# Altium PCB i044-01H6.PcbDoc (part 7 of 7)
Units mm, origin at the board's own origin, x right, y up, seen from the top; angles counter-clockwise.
Board outline 42 x 29.01 mm, 8 copper layers (Top Layer, Mid-Layer 1, Mid-Layer 2, Mid-Layer 3, Mid-Layer 4, Mid-Layer 5, Mid-Layer 6, Bottom Layer), stack 1.474 mm thick; 235 components, 197 nets, 1006 pads, 1183 vias.
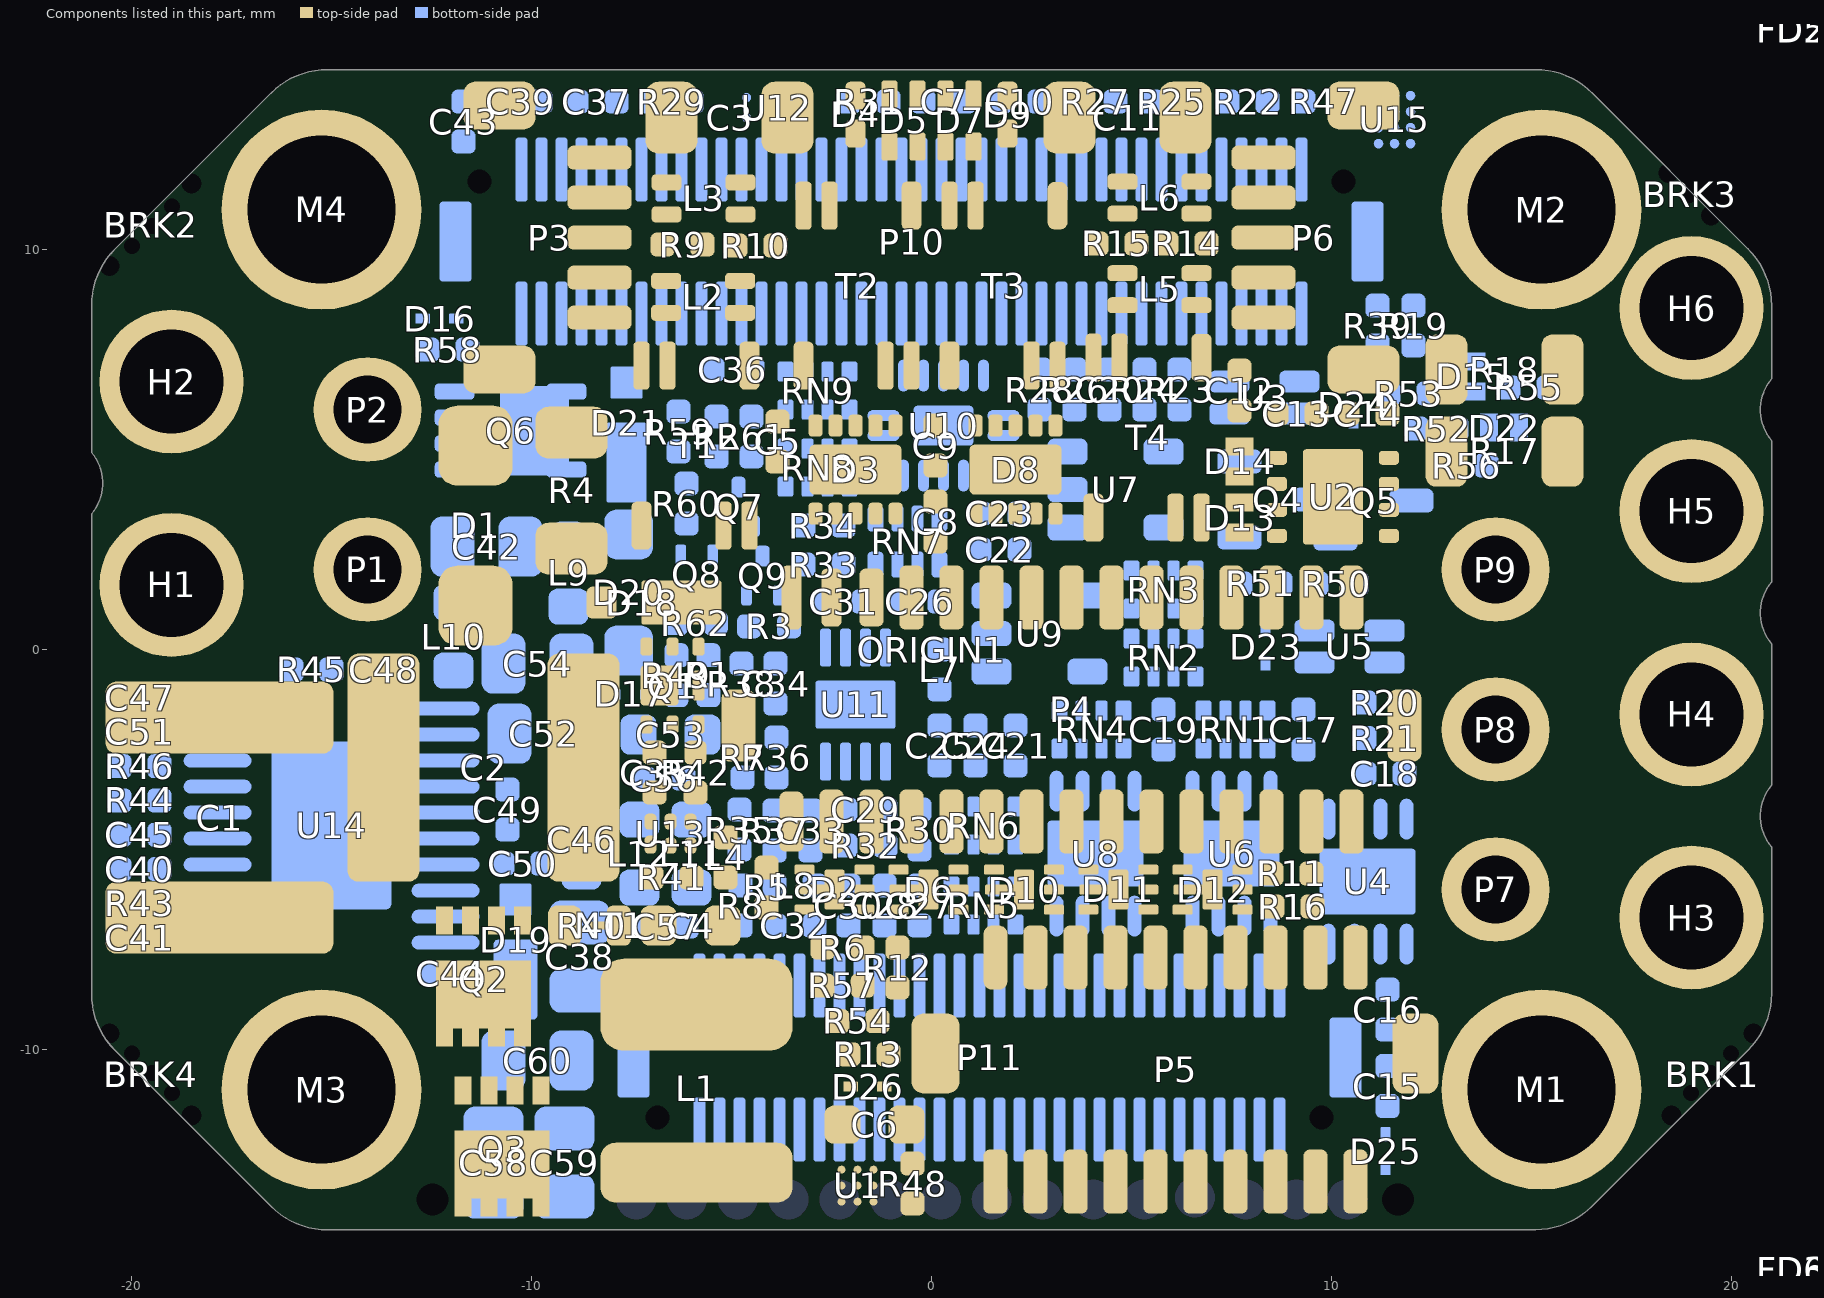
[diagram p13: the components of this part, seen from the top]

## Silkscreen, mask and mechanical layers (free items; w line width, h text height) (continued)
Mechanical 1:
  circle w0.1: c15.25,11 r1
  circle w0.1: c15.25,11 r2.5
  circle w0.1: c15.25,-11 r1
  circle w0.1: c15.25,-11 r2.5
  circle w0.1: c-15.25,-11 r1
  circle w0.1: c-15.25,-11 r2.5
  circle w0.1: c-15.25,11 r2.5
  circle w0.1: c-15.25,11 r1
  lines w0.1: -17.25,-11 -15.25,-11 ; -17.25,11 -15.25,11 ; -15.25,-13 -15.25,-11 ; -15.25,-9 -15.25,-11 ; -15.25,9 -15.25,11 ; -15.25,13 -15.25,11 ; -13.25,-11 -15.25,-11 ; -13.25,11 -15.25,11 ; 13.25,-11 15.25,-11 ; 13.25,11 15.25,11 ; 15.25,-13 15.25,-11 ; 15.25,-9 15.25,-11 ; 15.25,9 15.25,11 ; 15.25,13 15.25,11 ; 17.25,-11 15.25,-11 ; 17.25,11 15.25,11 ; -17.25,-13 -17.25,13.2 17.25,13.2 17.25,-13 -17.25,-13
Mechanical 2:
  lines w0.2: -15.102,-14.503 cw(c-15.102,-12.503) -16.516,-13.917 -20.414,-10.017 cw(c-19,-8.603) -21,-8.603 -21,3.389 ccw(c-21.919,4.161) -21,4.932 -21,8.6 cw(c-19,8.6) -20.414,10.014 -16.514,13.913 cw(c-15.1,12.498) -15.1,14.498 15.1,14.502 ; -15.1,-14.502 15.1,-14.498 ccw(c15.1,-12.498) 16.514,-13.913 20.414,-10.014 ccw(c19,-8.6) 21,-8.6 21,-4.933 cw(c21.919,-4.161) 21,-3.39 21,0.147 cw(c21.919,0.919) 21,1.69 21,5.227 cw(c21.919,5.999) 21,6.77 21,8.603 ccw(c19,8.603) 20.414,10.017 16.517,13.915 cw(c16.519,13.917) 16.516,13.917 ccw(c15.102,12.503) 15.102,14.503
Mechanical 11:
  lines w0.3: 2.82,-5.475 2.82,-6.95 4.295,-6.95 ; 2.82,-2.425 2.82,-0.95 4.295,-0.95 ; 5.837,-9.018 5.862,-7.943 ; 6.712,-8.593 5.862,-7.943 ; 7.345,-6.95 8.82,-6.95 8.82,-5.475 ; 7.345,-0.95 8.82,-0.95 8.82,-2.425 ; 9.3,-15.025 5.862,-7.943
  text "PCB Label should be sticked on botom over U6 and U8" at 8.575,-18.85 h1.5
Mechanical 14:
  rectangle: -11.2,-10.65 -8.15,-7.475
Mechanical 16:
  drawing of 644 lines, arcs and shapes, not listed
  text "." at 215.4,144 h3
  text ".PCB_Revision" at 21.25,135.75 h1.2
  text "'.Print_Date'" at 41.069,135.75 h1.2
  text "Everest XCR Interface" at 55.25,135.75 h1.2
  text "TOOLING HOLES (x4)" at 154.033,131.144 h5
  text "3mm, NON PLATED" at 165.921,123.374 h5
  text "GLOBAL FIDUCIALS (x4)" at 154.033,113.589 h5
  text "On top and bottom" at 153.975,109.075 h5
  text "Internal (copper): 1mm" at 165.446,102.709 h5
  text "External : 4mm" at 165.446,97.209 h5
  text "Milled, 2.4 mm" at 171.953,85.782 h5
  text "All dimensions in mm" at 154.425,73.275 h5
  text "Scale:" at 154.425,68.275 h5
  text "50 mm" at 194.425,65.775 h5
  text "0" at 154.425,63.275 h5
  text "10 mm" at 161.425,63.275 h5
  text "Side plating" at -6.9,42 h3
  text "INGENIA" at -16.8,3.6 h0.9 r270
  text "Breakaway tabs" at 94.5,3 h3
  text "Logo indicates TOP orientation" at -18.23,-4.19 h3
  text "." at -34.1,-37 h3
Drill Drawing:
  circle w0.254: c-37.457,36.699 r0.277
  circle w0.254: c-37.457,36.699 r0.462
  circle w0.254: c-37.457,22.138 r0.462
  lines w0.2: -38.784,18.972 62.382,18.972 ; -38.784,37.693 62.382,37.693 ; -33.44,16.892 -33.44,39.773 ; -28.102,16.892 -28.102,39.773 ; -18.415,16.892 -18.415,39.773 ; -14.271,16.892 -14.271,39.773 ; -8.238,16.892 -8.238,39.773 ; 3.198,16.892 3.198,39.773 ; 8.142,16.892 8.142,39.773 ; 14.599,16.892 14.599,39.773 ; 35.374,16.892 35.374,39.773 ; 41.859,16.892 41.859,39.773 ; 51.944,16.892 51.944,39.773 ; -38.784,16.892 62.382,16.892 62.382,39.773 -38.784,39.773 -38.784,16.892
  lines w0.254: -37.919,19.827 -37.688,19.827 -37.688,19.596 -37.226,19.596 -37.226,19.827 -36.995,19.827 -36.995,20.289 -37.226,20.289 -37.226,20.52 -37.688,20.52 -37.688,20.289 -37.919,20.289 -37.919,19.827 ; -37.919,24.218 -37.457,23.756 -36.995,24.218 -37.457,24.681 -37.919,24.218 ; -37.919,25.836 -36.995,25.836 -36.995,26.761 -37.919,26.761 -37.919,25.836 ; -37.919,28.147 -37.688,28.147 -37.457,27.916 -37.226,28.147 -36.995,28.147 -37.226,28.379 -36.995,28.61 -37.226,28.61 -37.457,28.841 -37.688,28.61 -37.919,28.61 -37.688,28.379 -37.919,28.147 ; -37.919,30.921 -36.995,30.921 -37.457,29.996 -37.919,30.921 ; -37.919,32.076 -37.919,32.308 -37.688,32.539 -37.919,32.77 -37.919,33.001 -37.688,33.001 -37.457,32.77 -37.226,33.001 -36.995,33.001 -36.995,32.77 -37.226,32.539 -36.995,32.308 -36.995,32.076 -37.226,32.076 -37.457,32.308 -37.688,32.076 -37.919,32.076 ; -37.919,34.156 -37.457,34.388 -36.995,34.156 -37.226,34.619 -36.995,35.081 -37.457,34.85 -37.919,35.081 -37.688,34.619 -37.919,34.156 ; -37.734,26.021 -37.179,26.021 -37.179,26.576 -37.734,26.576 -37.734,26.021
  text "Symbol" at -37.536,38.317 h1.21
  text "Count" at -32.816,38.317 h1.21
  text "Hole Size" at -27.478,38.317 h1.21
  text "Plated" at -17.791,38.317 h1.21
  text "Hole Type" at -13.647,38.317 h1.21
  text "Drill Layer Pair" at -7.614,38.317 h1.21
  text "Via/Pad" at 3.823,38.317 h1.21
  text "Pad Shape" at 8.766,38.317 h1.21
  text "Template" at 15.223,38.317 h1.21
  text "Description" at 35.998,38.317 h1.21
  text "Hole Tolerance (+)" at 42.483,38.317 h1.21
  text "Hole Tolerance (-)" at 52.568,38.317 h1.21
  text "2" at -32.816,36.237 h1
  text "0.800mm (31.50mil)" at -27.478,36.237 h1
  text "NPTH" at -17.791,36.237 h1
  text "Round" at -13.647,36.237 h1
  text "Top Layer - Bottom Layer" at -7.614,36.237 h1
  text "Pad" at 3.823,36.237 h1
  text "Rounded" at 8.766,36.237 h1
  text "c0hn80m-1" at 15.223,36.237 h1
  text "4" at -32.816,34.156 h1
  text "0.600mm (23.62mil)" at -27.478,34.156 h1
  text "NPTH" at -17.791,34.156 h1
  text "Round" at -13.647,34.156 h1
  text "Top Layer - Bottom Layer" at -7.614,34.156 h1
  text "Pad" at 3.823,34.156 h1
  text "Rounded" at 8.766,34.156 h1
  text "c0hn60" at 15.223,34.156 h1
  text "4" at -32.816,32.076 h1
  text "3.700mm (145.67mil)" at -27.478,32.076 h1
  text "PTH" at -17.791,32.076 h1
  text "Round" at -13.647,32.076 h1
  text "Top Layer - Bottom Layer" at -7.614,32.076 h1
  text "Pad" at 3.823,32.076 h1
  text "Rounded" at 8.766,32.076 h1
  text "c500h370z400x560m500mx560p-1_2843438878" at 15.223,32.076 h1
  text "5" at -32.816,29.996 h1
  text "1.700mm (66.93mil)" at -27.478,29.996 h1
  text "PTH" at -17.791,29.996 h1
  text "Round" at -13.647,29.996 h1
  text "Top Layer - Bottom Layer" at -7.614,29.996 h1
  text "Pad" at 3.823,29.996 h1
  text "Rounded" at 8.766,29.996 h1
  text "r270_260h170r100" at 15.223,29.996 h1
  text "6" at -32.816,27.916 h1
  text "2.600mm (102.36mil)" at -27.478,27.916 h1
  text "PTH" at -17.791,27.916 h1
  text "Round" at -13.647,27.916 h1
  text "Top Layer - Bottom Layer" at -7.614,27.916 h1
  text "Pad" at 3.823,27.916 h1
  text "Rounded" at 8.766,27.916 h1
  text "(Mixed)" at 15.223,27.916 h1
  text "8" at -32.816,25.836 h1
  text "0.500mm (19.69mil)" at -27.478,25.836 h1
  text "NPTH" at -17.791,25.836 h1
  text "Round" at -13.647,25.836 h1
  text "Top Layer - Bottom Layer" at -7.614,25.836 h1
  text "Pad" at 3.823,25.836 h1
  text "Rounded" at 8.766,25.836 h1
  text "c0hn50m-1" at 15.223,25.836 h1
  text "10" at -32.816,23.756 h1
  text "0.400mm (15.75mil)" at -27.478,23.756 h1
  text "NPTH" at -17.791,23.756 h1
  text "Round" at -13.647,23.756 h1
  text "Top Layer - Bottom Layer" at -7.614,23.756 h1
  text "Pad" at 3.823,23.756 h1
  text "Rounded" at 8.766,23.756 h1
  text "c0hn40m-1" at 15.223,23.756 h1
  text "276" at -32.816,21.676 h1
  text "0.200mm (7.87mil)" at -27.478,21.676 h1
  text "PTH" at -17.791,21.676 h1
  text "Round" at -13.647,21.676 h1
  text "Mid-Layer 1 - Mid-Layer 6" at -7.614,21.676 h1
  text "Via" at 3.823,21.676 h1
  text "Rounded" at 8.766,21.676 h1
  text "v60h20m45" at 15.223,21.676 h1
  text "907" at -32.816,19.596 h1
  text "0.100mm (3.94mil)" at -27.478,19.596 h1
  text "PTH" at -17.791,19.596 h1
  text "Round" at -13.647,19.596 h1
  text "(Mixed)" at -7.614,19.596 h1
  text "Via" at 3.823,19.596 h1
  text "Rounded" at 8.766,19.596 h1
  text "v30h10m12" at 15.223,19.596 h1
  text "1222 Total" at -32.816,17.516 h1
Mechanical 17:
  rectangle: -17.5,-0.457 -12.5,8.179
  rectangle: 12.522,-7.62 17.145,3.607
  rectangle: -13.051,6.55 -8.25,14.503
  region: 13.051,14.529 8.25,14.529 8.25,6.6 13.051,6.6
  region: 12.624,-4.65 12.624,2.453 -5.5,2.453 -5.5,-4.65
  region: -21.006,3.404 ccw(c-21.724,4.105) -20.726,4.216 ccw(c-22.186,4.053) -21.006,4.928 -21.006,8.6 -16.866,8.6 -16.866,-0.457 -21.006,-0.457
  region: 15.102,14.529 cw(c15.031,12.429) 16.517,13.915 20.414,10.017 cw(c19,8.603) 21,8.603 21,8.179 12.249,8.179 12.249,14.529
  region: -16.514,13.913 cw(c-15.087,12.484) -15.1,14.503 -12.225,14.503 -12.225,8.026 -21,8.026 -21,8.6 cw(c-18.991,8.6) -20.416,10.016
  region: 21,-3.39 ccw(c22.013,-4.185) 20.726,-4.14 ccw(c21.894,-4.181) 21,-4.933 21,-8.814 16.866,-8.814 16.866,8.23 21,8.23 21,6.77 ccw(c21.735,6.07) 20.72,6.044 ccw(c21.984,6.021) 21,5.227 21,1.69 ccw(c22.356,0.728) 20.746,1.142 ccw(c21.624,0.916) 20.757,0.651 ccw(c22.504,1.185) 21,0.147
  region: -20.411,-10.014 cw(c-19.017,-8.603) -21,-8.603 -21,-7.979 -11.9,-7.979 -11.9,-14.503 -15.1,-14.503 cw(c-15.103,-12.508) -16.516,-13.917
  region: 21,-8.6 cw(c19.001,-8.6) 20.414,-10.014 16.514,-13.913 cw(c15.088,-12.486) 15.1,-14.503 -0.4,-14.503 -0.4,-7.35 21,-7.35
  text "Do not apply coating  / in the highlighted areas.  / Cover them before the / coating process" at -17.697,15.648 h1.52
Mechanical 18:
  rectangle: 12.243,-7.62 17.145,3.607
  rectangle: -17.5,0.406 -12.5,8.179
  region: 10.15,-12.3 10.15,-8.1 -7.25,-8.1 -7.25,-12.3
  region: 10.7,8.1 10.7,12.3 -11.7,12.3 -11.7,8.1
  region: 21,-3.39 ccw(c22.013,-4.185) 20.726,-4.14 ccw(c21.894,-4.181) 21,-4.933 21,-8.814 16.866,-8.814 16.866,8.23 21,8.23 21,6.77 ccw(c21.735,6.07) 20.72,6.044 ccw(c21.984,6.021) 21,5.227 21,1.69 ccw(c22.356,0.728) 20.746,1.142 ccw(c21.624,0.916) 20.757,0.651 ccw(c22.504,1.185) 21,0.147
  region: -16.514,13.913 cw(c-15.087,12.484) -15.1,14.503 -12.225,14.503 -12.225,8.026 -21,8.026 -21,8.6 cw(c-18.991,8.6) -20.416,10.016
  region: -21.006,3.404 ccw(c-21.724,4.105) -20.726,4.216 ccw(c-22.186,4.053) -21.006,4.928 -21.006,8.6 -16.866,8.6 -16.866,-0.457 -21.006,-0.457
  region: 15.102,14.529 cw(c15.031,12.429) 16.517,13.915 20.414,10.017 cw(c19,8.603) 21,8.603 21,8.001 12.249,8.001 12.249,14.529
  region: 21,-8.6 cw(c19.001,-8.6) 20.414,-10.014 16.514,-13.913 cw(c15.088,-12.486) 15.1,-14.503 12.243,-14.503 12.243,-7.35 21,-7.35
  region: -20.411,-10.014 cw(c-19.017,-8.603) -21,-8.603 -21,-7.979 -11.9,-7.979 -11.9,-14.503 -15.1,-14.503 cw(c-15.103,-12.508) -16.516,-13.917
  text "Do not apply coating  / in the highlighted areas.  / Cover them before the / coating process" at 19.323,15.648 h1.52
Mechanical 20:
  drawing of 174 lines, arcs and shapes, not listed
  text "INTERNAL LOGIC" at 1.44,32.301 h1.52
  text "MAX:" at 1.44,29.571 h1.52
  text "5 V" at 8.94,29.321 h1.52
  text "2 A" at 8.94,26.821 h1.52
  text "STO INPUT" at 31.599,20.957 h1.52
  text "PE" at 12.254,20.254 h1.52
  text "PE" at -9.046,19.503 h1.52
  text "MAX:" at 31.849,18.402 h1.52
  text "30 V" at 39.099,18.402 h1.52
  text "5 mA" at 39.099,16.152 h1.52
  text "POW SUP" at -44.246,8.109 h1.52
  text "MAX:" at -44.246,5.379 h1.52
  text "80 V" at -36.996,5.379 h1.52
  text "MOTOR PHASES" at 26.254,3.684 h1.52
  text "60 A" at -36.996,3.129 h1.52
  text "MAX:" at 26.504,1.129 h1.52
  text "80 V" at 33.754,1.129 h1.52
  text "60 A" at 33.754,-1.121 h1.52
  text "PE" at 25.254,-12.396 h1.52
  text "PE" at -23.746,-16.996 h1.52
  text "LOGIC SUPPLY IN" at -13.996,-22.566 h1.52
  text "MAX:" at -13.996,-25.296 h1.52
  text "50 V" at -6.746,-25.296 h1.52
  text "1.5 A @ 8 V" at -6.703,-27.955 h1.52
Mechanical 21:
  circle w0.5: c15.25,-11 r2.3
  circle w0.5: c-15.25,11 r2.3
  circle w0.5: c-15.25,-11 r2.3
  lines w0.2: -33.553,1.6 -11.05,-12.079 ; -29,2.728 -9.99,-8.721 ; -29,6.457 -21,-0.08 ; -20.265,-15.25 -16.893,-12.61 ; -18.525,13.625 -17,12.492 ; -5.35,-0.101 -5.125,-19.858 ; -0.9,15 13,25.567 ; 13.862,19.474 15.035,13.29 ; 16.517,13.915 cw(c16.519,13.917) 16.516,13.917 ; 16.942,7.474 30.095,19 ; 17.547,-11.038 24.25,-11.625 ; 21.5,-1.11 24.75,1.825
  lines w0.5: -21,-8.603 ccw(c-19,-8.603) -20.414,-10.017 -16.516,-13.917 ccw(c-15.102,-12.503) -15.102,-14.503 ; -21,8.719 -12.467,8.698 ; -15.1,-14.502 15.1,-14.498 ccw(c15.1,-12.498) 16.514,-13.913 20.414,-10.014 ccw(c19,-8.6) 21,-8.6 21,-4.933 cw(c21.919,-4.161) 21,-3.39 21,0.147 cw(c21.919,0.919) 21,1.69 21,5.227 cw(c21.919,5.999) 21,6.77 21,8.603 ccw(c19,8.603) 20.414,10.017 16.517,13.915 ; -14.178,14.448 -12.467,12.738 -12.467,8.71 -9.986,6.188 -10.017,2.427 -7.53,-0.101 ; -12.95,-14.517 -12.95,-11 ; -12.95,-13.083 -10.191,-11.625 -8.907,-11.7 -8.197,-12.331 -8.125,-14.501 ; -10.01,3.32 -8.816,3.32 -8.225,2.728 -8.225,2.45 -7,1.225 -4.475,1.225 -3.85,0.6 -3.85,0.369 -4.32,-0.101 -7.53,-0.101 ; -8.035,-3.541 -7.554,-3.068 -7.53,-0.101 ; -8.027,-3.55 -8.024,-4.75 -8.907,-4.75 -10.249,-3.247 -11.74,-3.235 -14.479,-5.93 -14.495,-7.843 -14.989,-8.328 -21,-8.328 -21,-8.281 -21,3.389 ccw(c-21.919,4.161) -21,4.932 -21,8.6 cw(c-19,8.6) -20.414,10.014 -16.514,13.913 cw(c-15.1,12.498) -15.1,14.498 15.1,14.502 ; 12.475,1.3 11.05,-0.125 8.665,-0.125 8.15,0.39 8.15,1.55 8.425,1.825 8.85,1.825 9.275,2.25 9.675,2.25 10.165,1.76 10.4,1.76 11.3,2.66 11.3,4.65 11.75,5.1 11.75,7.055 12.417,7.722 13.495,7.722 14.575,8.801 ; 12.953,-14.499 12.953,-10.875 ; 13.918,12.875 13.918,14.501 ; 15.102,14.503 cw(c15.102,12.503) 16.516,13.917 ; 19.645,10.779 18.681,10.786 16.992,12.502 ccw(c15.25,11) 15.25,8.7 15.9,8.603 18.013,6.313 20.761,6.313 ; 20.331,-9.525 17.742,-9.525 16.342,-8.125 13.1,-8.125 12.45,-7.475 12.45,3.475 13.1,4.125 16.075,4.125 17.888,6 20.625,6 ; -46.25,1.649 -29,1.649 -29,11.265 -46.25,11.382 -46.25,1.649 ; -15.075,-29.75 12.097,-29.75 12.097,-19.975 -15.075,-19.791 -15.075,-29.75 ; -9.99,-8.721 -9.723,-9.508 -8.332,-9.977 -7.874,-9.639 -7.874,-8.947 -9.297,-8.449 -9.99,-8.721 ; 0.25,25.567 25.75,25.567 25.75,34.773 0.25,34.946 0.25,25.567 ; 24.75,-2.751 24.75,6.642 46.5,6.494 46.5,-2.751 24.75,-2.751 ; 30.095,14.522 47.75,14.522 47.75,23.795 30.095,23.915 30.095,14.522
  text "INTERNAL LOGIC" at 1.44,32.301 h1.52
  text "MAX:" at 1.44,29.571 h1.52
  text "5 V" at 8.94,29.321 h1.52
  text "2 A" at 8.94,26.821 h1.52
  text "STO INPUT" at 31.599,20.957 h1.52
  text "PE" at 12.279,20.254 h1.52
  text "MAX:" at 31.849,18.402 h1.52
  text "30 V" at 39.099,18.402 h1.52
  text "5 mA" at 39.099,16.152 h1.52
  text "PE" at -21.996,13.529 h1.52
  text "POW SUP" at -44.246,8.109 h1.52
  text "MAX:" at -44.246,5.379 h1.52
  text "80 V" at -36.996,5.379 h1.52
  text "MOTOR PHASES" at 26.254,3.684 h1.52
  text "60 A" at -36.996,3.129 h1.52
  text "MAX:" at 26.504,1.129 h1.52
  text "80 V" at 33.754,1.129 h1.52
  text "60 A" at 33.754,-1.121 h1.52
  text "PE" at 25.254,-12.396 h1.52
  text "PE" at -23.746,-16.996 h1.52
  text "LOGIC SUPPLY IN" at -13.996,-22.566 h1.52
  text "MAX:" at -13.996,-25.296 h1.52
  text "50 V" at -6.746,-25.296 h1.52
  text "1.5 A @ 8 V" at -6.703,-27.955 h1.52
Mechanical 22:
  circle w0.5: c-15.25,-11.085 r2.3
  circle w0.5: c-15.25,10.915 r2.3
  circle w0.5: c15.25,-11.085 r2.3
  lines w0.2: -34.417,1.564 -11.65,-12.875 ; -29,4.3 -9.675,-2.867 ; -29,6.373 -21.5,4.623 ; -20.265,-15.335 -16.893,-12.694 ; -18.525,13.54 -17,12.408 ; -0.1,15 9.25,25.482 ; 13.862,19.389 15.035,13.205 ; 14.649,8.25 30.095,19.134 ; 16.517,13.915 cw(c16.519,13.917) 16.516,13.917 ; 17.547,-11.122 24.25,-11.71 ; 21.5,-1.195 24.75,1.74
  lines w0.5: -20.85,-0.625 -17.75,-0.625 -16.047,0.15 -13.25,0.169 -12.475,0.875 -12.475,8.25 ; -19.778,10.575 -17.525,10.575 ; -18.577,-11.414 -17.525,-11.425 ; -15.102,-14.503 cw(c-15.102,-12.503) -16.516,-13.917 -20.414,-10.017 cw(c-19,-8.603) -21,-8.603 -21,3.389 ccw(c-21.919,4.161) -21,4.932 -21,8.6 cw(c-19,8.6) -20.414,10.014 -16.514,13.913 cw(c-15.1,12.498) -15.1,14.498 15.1,14.502 ; -15.1,-14.502 15.1,-14.498 ccw(c15.1,-12.498) 16.514,-13.913 20.414,-10.014 ccw(c19,-8.6) 21,-8.6 21,-4.933 cw(c21.919,-4.161) 21,-3.39 21,0.147 cw(c21.919,0.919) 21,1.69 21,5.227 cw(c21.919,5.999) 21,6.77 21,8.603 ccw(c19,8.603) 20.414,10.017 16.517,13.915 ; -13.685,9.23 -12.475,8.25 ; -13.685,14.499 -13.685,13.956 -12.467,12.738 ; -12.95,-14.517 -12.95,-11 ; -12.475,12.75 -12.475,8.25 ; -12.014,-14.503 -12.014,-13.164 -11.728,-12.878 -8.95,-12.878 -8.6,-13.228 -8.6,-14.501 ; 12.475,1.75 10.71,-0.015 8.875,-0.015 8.15,0.71 8.15,1.275 8.875,2 10.25,2 11.3,3.05 11.3,6.4 13.15,8.25 16.147,8.25 ; 12.953,-14.499 12.953,-10.875 ; 13.185,-8.21 13.25,-9.949 ; 13.918,12.875 13.918,14.501 ; 15.102,14.503 cw(c15.102,12.503) 16.516,13.917 ; 19.816,10.615 18.758,10.623 16.992,12.417 ccw(c15.25,10.915) 15.25,8.615 15.9,8.518 18.013,6.228 20.741,6.228 ; 20.625,5.915 17.888,5.915 16.075,4.04 13.1,4.04 12.45,3.39 12.45,-7.56 13.1,-8.21 16.342,-8.21 17.742,-9.61 20.662,-9.61 ; -46.25,1.564 -46.25,11.298 -29,11.181 -29,1.565 -46.25,1.564 ; -9.99,-8.721 -9.297,-8.449 -7.874,-8.947 -7.874,-9.639 -8.332,-9.977 -9.723,-9.508 -9.99,-8.721 ; -9.959,-3.572 -9.675,-2.867 -8.028,-2.979 -8.024,-4.75 -8.907,-4.75 -9.959,-3.572 ; 0.25,25.482 0.25,34.861 25.75,34.688 25.75,25.483 0.25,25.482 ; 24.75,-2.836 46.5,-2.835 46.5,6.409 24.75,6.557 24.75,-2.836 ; 30.095,14.437 30.095,23.83 47.75,23.71 47.75,14.438 30.095,14.437
  text "INTERNAL LOGIC" at 1.44,32.216 h1.52
  text "MAX:" at 1.44,29.486 h1.52
  text "5 V" at 8.94,29.236 h1.52
  text "2 A" at 8.94,26.736 h1.52
  text "STO INPUT" at 31.599,20.872 h1.52
  text "PE" at 12.279,20.169 h1.52
  text "MAX:" at 31.849,18.317 h1.52
  text "30 V" at 39.099,18.317 h1.52
  text "5 mA" at 39.099,16.067 h1.52
  text "PE" at -21.996,13.444 h1.52
  text "POW SUP" at -44.246,8.024 h1.52
  text "MAX:" at -44.246,5.294 h1.52
  text "80 V" at -36.996,5.294 h1.52
  text "MOTOR PHASES" at 26.254,3.599 h1.52
  text "60 A" at -36.996,3.044 h1.52
  text "MAX:" at 26.504,1.044 h1.52
  text "80 V" at 33.754,1.044 h1.52
  text "60 A" at 33.754,-1.206 h1.52
  text "PE" at 25.254,-12.481 h1.52
  text "PE" at -23.746,-17.081 h1.52
Mechanical 23:
  circle w0.5: c15.25,-11 r2.3
  circle w0.5: c-15.25,11 r2.3
  circle w0.5: c-15.25,-11 r2.3
  lines w0.2: -29,6.373 -20.746,4.447 ; -20.265,-15.25 -16.893,-12.61 ; -18.525,13.625 -17,12.492 ; -0.1,15 9.25,25.482 ; 13.862,19.474 15.035,13.29 ; 16.517,13.915 cw(c16.519,13.917) 16.516,13.917 ; 17.547,-11.038 24.25,-11.625 ; 21.093,-1.478 24.75,1.825
  lines w0.5: -21,-0.625 -17.75,-0.625 -16.047,0.15 -13.25,0.169 -12.475,0.875 -12.475,8.25 ; -19.837,10.575 -17.525,10.575 ; -19,-11.41 -17.525,-11.425 ; -15.102,-14.503 cw(c-15.102,-12.503) -16.516,-13.917 -20.414,-10.017 cw(c-19,-8.603) -21,-8.603 -21,3.389 ccw(c-21.919,4.161) -21,4.932 -21,8.6 cw(c-19,8.6) -20.414,10.014 -16.514,13.913 cw(c-15.1,12.498) -15.1,14.498 15.1,14.502 ; -15.1,-14.502 15.1,-14.498 ccw(c15.1,-12.498) 16.514,-13.913 20.414,-10.014 ccw(c19,-8.6) 21,-8.6 21,-4.933 cw(c21.919,-4.161) 21,-3.39 21,0.147 cw(c21.919,0.919) 21,1.69 21,5.227 cw(c21.919,5.999) 21,6.77 21,8.603 ccw(c19,8.603) 20.414,10.017 16.517,13.915 ; -13.685,9.23 -12.475,8.25 ; -13.685,14.499 -13.685,13.956 -12.467,12.738 ; -12.95,-14.517 -12.95,-11 ; -12.475,12.75 -12.475,8.25 ; 12.45,3.39 12.45,-7.56 13.1,-8.21 ; 12.953,-14.32 12.953,-10.875 ; 13.185,-8.21 13.25,-9.949 ; 13.258,12.165 13.258,14.501 ; 13.267,4.125 13.267,9.878 ; 15.102,14.503 cw(c15.102,12.503) 16.516,13.917 ; 20.117,10.312 19.658,10.779 18.681,10.786 16.992,12.502 ccw(c15.25,11) 15.25,8.7 15.9,8.603 18.013,6.313 20.761,6.313 ; 20.625,6 17.888,6 16.075,4.125 13.1,4.125 12.45,3.475 12.45,-7.475 13.1,-8.125 16.342,-8.125 17.742,-9.525 20.663,-9.525 ; -46.25,1.564 -46.25,11.298 -29,11.181 -29,1.565 -46.25,1.564 ; 0.25,25.482 0.25,34.861 25.75,34.688 25.75,25.483 0.25,25.482 ; 24.75,-2.751 24.75,6.642 46.5,6.494 46.5,-2.751 24.75,-2.751
  text "INTERNAL LOGIC" at 1.44,32.216 h1.52
  text "MAX:" at 1.44,29.486 h1.52
  text "5 V" at 8.94,29.236 h1.52
  text "2 A" at 8.94,26.736 h1.52
  text "PE" at 12.279,20.254 h1.52
  text "PE" at -21.996,13.529 h1.52
  text "POW SUP" at -44.246,8.024 h1.52
  text "MAX:" at -44.246,5.294 h1.52
  text "80 V" at -36.996,5.294 h1.52
  text "MOTOR PHASES" at 26.254,3.684 h1.52
  text "60 A" at -36.996,3.044 h1.52
  text "MAX:" at 26.504,1.129 h1.52
  text "80 V" at 33.754,1.129 h1.52
  text "60 A" at 33.754,-1.121 h1.52
  text "PE" at 25.254,-12.396 h1.52
  text "PE" at -23.746,-16.996 h1.52
Mechanical 24:
  circle w0.5: c15.25,-11 r2.3
  circle w0.5: c-15.25,11 r2.3
  circle w0.5: c-15.25,-11 r2.3
  lines w0.2: -29,6.373 -20.746,4.447 ; -20.265,-15.25 -16.893,-12.61 ; -18.525,13.625 -17,12.492 ; -0.1,15 9.25,25.482 ; 13.862,19.474 15.035,13.29 ; 16.517,13.915 cw(c16.519,13.917) 16.516,13.917 ; 17.547,-11.038 24.25,-11.625 ; 21.093,-1.478 24.75,1.825
  lines w0.5: -19.837,10.575 -17.525,10.575 ; -19,-11.41 -17.525,-11.425 ; -15.102,-14.503 cw(c-15.102,-12.503) -16.516,-13.917 -20.414,-10.017 cw(c-19,-8.603) -21,-8.603 -21,3.389 ccw(c-21.919,4.161) -21,4.932 -21,8.6 cw(c-19,8.6) -20.414,10.014 -16.514,13.913 cw(c-15.1,12.498) -15.1,14.498 15.1,14.502 ; -15.1,-14.502 15.1,-14.498 ccw(c15.1,-12.498) 16.514,-13.913 20.414,-10.014 ccw(c19,-8.6) 21,-8.6 21,-4.933 cw(c21.919,-4.161) 21,-3.39 21,0.147 cw(c21.919,0.919) 21,1.69 21,5.227 cw(c21.919,5.999) 21,6.77 21,8.603 ccw(c19,8.603) 20.414,10.017 16.517,13.915 ; -13.685,9.23 -12.475,8.25 ; -13.685,14.499 -13.685,13.956 -12.467,12.738 ; -12.95,-14.517 -12.95,-11 ; -12.475,12.75 -12.475,8.25 ; -7.47,-14.501 -7.47,-8.205 -8.125,-7.55 -8.125,-5.875 -7.775,-5.525 -7.775,-0.023 -8.673,0.875 -12.2,0.875 -12.475,1.15 -12.475,8.25 ; 12.45,3.39 12.45,-7.56 13.1,-8.21 ; 12.953,-14.32 12.953,-10.875 ; 13.185,-8.21 13.25,-9.949 ; 13.258,12.165 13.258,14.501 ; 13.267,4.125 13.267,9.878 ; 15.102,14.503 cw(c15.102,12.503) 16.516,13.917 ; 20.117,10.312 19.658,10.779 18.681,10.786 16.992,12.502 ccw(c15.25,11) 15.25,8.7 15.9,8.603 18.013,6.313 20.761,6.313 ; 20.625,6 17.888,6 16.075,4.125 13.1,4.125 12.45,3.475 12.45,-7.475 13.1,-8.125 16.342,-8.125 17.742,-9.525 20.663,-9.525 ; -46.25,1.564 -46.25,11.298 -29,11.181 -29,1.565 -46.25,1.564 ; 0.25,25.482 0.25,34.861 25.75,34.688 25.75,25.483 0.25,25.482 ; 24.75,-2.751 24.75,6.642 46.5,6.494 46.5,-2.751 24.75,-2.751
  text "INTERNAL LOGIC" at 1.44,32.216 h1.52
  text "MAX:" at 1.44,29.486 h1.52
  text "5 V" at 8.94,29.236 h1.52
  text "2 A" at 8.94,26.736 h1.52
  text "PE" at 12.279,20.254 h1.52
  text "PE" at -21.996,13.529 h1.52
  text "POW SUP" at -44.246,8.024 h1.52
  text "MAX:" at -44.246,5.294 h1.52
  text "80 V" at -36.996,5.294 h1.52
  text "MOTOR PHASES" at 26.254,3.684 h1.52
  text "60 A" at -36.996,3.044 h1.52
  text "MAX:" at 26.504,1.129 h1.52
  text "80 V" at 33.754,1.129 h1.52
  text "60 A" at 33.754,-1.121 h1.52
  text "PE" at 25.254,-12.396 h1.52
  text "PE" at -23.746,-16.996 h1.52
Mechanical 25:
  circle w0.5: c-15.25,-11 r2.3
  circle w0.5: c-15.25,11 r2.3
  circle w0.5: c15.25,-11 r2.3
  lines w0.2: -29,4.161 -10.636,-13.037 ; -29,6.373 -20.746,4.447 ; -20.265,-15.25 -16.893,-12.61 ; -18.525,13.625 -17,12.492 ; -0.1,15 9.25,25.482 ; 13.862,19.474 15.035,13.29 ; 16.517,13.915 cw(c16.519,13.917) 16.516,13.917 ; 17.547,-11.038 24.25,-11.625 ; 21.093,-1.478 24.75,1.825
  lines w0.5: -21,-0.625 -17.75,-0.625 -16.047,0.15 -13.25,0.169 -12.475,0.875 -12.475,8.25 ; -19.837,10.575 -17.525,10.575 ; -19,-11.41 -17.525,-11.425 ; -15.102,-14.503 cw(c-15.102,-12.503) -16.516,-13.917 -20.414,-10.017 cw(c-19,-8.603) -21,-8.603 -21,3.389 ccw(c-21.919,4.161) -21,4.932 -21,8.6 cw(c-19,8.6) -20.414,10.014 -16.514,13.913 cw(c-15.1,12.498) -15.1,14.498 15.1,14.502 ; -15.1,-14.502 15.1,-14.498 ccw(c15.1,-12.498) 16.514,-13.913 20.414,-10.014 ccw(c19,-8.6) 21,-8.6 21,-4.933 cw(c21.919,-4.161) 21,-3.39 21,0.147 cw(c21.919,0.919) 21,1.69 21,5.227 cw(c21.919,5.999) 21,6.77 21,8.603 ccw(c19,8.603) 20.414,10.017 16.517,13.915 ; -13.685,9.23 -12.475,8.25 ; -13.685,14.499 -13.685,13.956 -12.467,12.738 ; -12.95,-14.517 -12.95,-11 ; -12.475,12.75 -12.475,8.25 ; -11.502,-14.497 -11.502,-13.527 -11.05,-13.075 -9.005,-13.075 -8.6,-13.48 -8.6,-14.501 ; 12.45,3.39 12.45,-7.56 13.1,-8.21 ; 12.953,-14.32 12.953,-10.875 ; 13.185,-8.21 13.25,-9.949 ; 13.258,12.165 13.258,14.501 ; 13.267,4.125 13.267,9.878 ; 15.102,14.503 cw(c15.102,12.503) 16.516,13.917 ; 20.117,10.312 19.658,10.779 18.681,10.786 16.992,12.502 ccw(c15.25,11) 15.25,8.7 15.9,8.603 18.013,6.313 20.761,6.313 ; 20.625,6 17.888,6 16.075,4.125 13.1,4.125 12.45,3.475 12.45,-7.475 13.1,-8.125 16.342,-8.125 17.742,-9.525 20.663,-9.525 ; -46.25,1.564 -29,1.565 -29,11.181 -46.25,11.298 -46.25,1.564 ; 0.25,25.482 25.75,25.483 25.75,34.688 0.25,34.861 0.25,25.482 ; 24.75,-2.751 46.5,-2.751 46.5,6.494 24.75,6.642 24.75,-2.751
  text "INTERNAL LOGIC" at 1.44,32.216 h1.52
  text "MAX:" at 1.44,29.486 h1.52
  text "5 V" at 8.94,29.236 h1.52
  text "2 A" at 8.94,26.736 h1.52
  text "PE" at 12.279,20.254 h1.52
  text "PE" at -21.996,13.529 h1.52
  text "POW SUP" at -44.246,8.024 h1.52
  text "MAX:" at -44.246,5.294 h1.52
  text "80 V" at -36.996,5.294 h1.52
  text "MOTOR PHASES" at 26.254,3.684 h1.52
  text "60 A" at -36.996,3.044 h1.52
  text "MAX:" at 26.504,1.129 h1.52
  text "80 V" at 33.754,1.129 h1.52
  text "60 A" at 33.754,-1.121 h1.52
  text "PE" at 25.254,-12.396 h1.52
  text "PE" at -23.746,-16.996 h1.52
Mechanical 26:
  drawing of 165 lines, arcs and shapes, not listed
  text "INTERNAL LOGIC" at 1.44,32.216 h1.52
  text "MAX:" at 1.44,29.486 h1.52
  text "5 V" at 8.94,29.236 h1.52
  text "2 A" at 8.94,26.736 h1.52
  text "STO INPUT" at 31.599,20.957 h1.52
  text "PE" at 12.279,20.254 h1.52
  text "MAX:" at 31.849,18.402 h1.52
  text "30 V" at 39.099,18.402 h1.52
  text "5 mA" at 39.099,16.152 h1.52
  text "PE" at -21.996,13.529 h1.52
  text "POW SUP" at -44.246,8.024 h1.52
  text "MAX:" at -44.246,5.294 h1.52
  text "80 V" at -36.996,5.294 h1.52
  text "MOTOR PHASES" at 26.254,3.684 h1.52
  text "60 A" at -36.996,3.044 h1.52
  text "MAX:" at 26.504,1.129 h1.52
  text "80 V" at 33.754,1.129 h1.52
  text "60 A" at 33.754,-1.121 h1.52
  text "PE" at 25.254,-12.396 h1.52
  text "PE" at -23.746,-16.996 h1.52
  text "LOGIC SUPPLY IN" at -13.996,-22.566 h1.52
  text "MAX:" at -13.996,-25.296 h1.52
  text "50 V" at -6.746,-25.296 h1.52
  text "1.5 A @ 8 V" at -6.703,-27.955 h1.52
Mechanical 27:
  drawing of 175 lines, arcs and shapes, not listed
  text "INTERNAL LOGIC" at 1.44,32.301 h1.52
  text "MAX:" at 1.44,29.571 h1.52
  text "5 V" at 8.94,29.321 h1.52
  text "2 A" at 8.94,26.821 h1.52
  text "STO INPUT" at 31.599,20.957 h1.52
  text "PE" at 12.279,20.254 h1.52
  text "MAX:" at 31.849,18.402 h1.52
  text "30 V" at 39.099,18.402 h1.52
  text "5 mA" at 39.099,16.152 h1.52
  text "PE" at -21.996,13.529 h1.52
  text "POW SUP" at -44.246,8.109 h1.52
  text "MAX:" at -44.246,5.379 h1.52
  text "80 V" at -36.996,5.379 h1.52
  text "MOTOR PHASES" at 26.254,3.684 h1.52
  text "60 A" at -36.996,3.129 h1.52
  text "MAX:" at 26.504,1.129 h1.52
  text "80 V" at 33.754,1.129 h1.52
  text "60 A" at 33.754,-1.121 h1.52
  text "PE" at 25.254,-12.396 h1.52
  text "PE" at -23.746,-16.996 h1.52
  text "LOGIC SUPPLY IN" at -13.996,-22.566 h1.52
  text "MAX:" at -13.996,-25.296 h1.52
  text "50 V" at -6.746,-25.296 h1.52
  text "1.5 A @ 8 V" at -6.703,-27.955 h1.52
Top CoatingMask:
  circle w1.5: c-19,-23 r0.75
  circle w1.5: c-14.1,2 r0.75
  circle w1.5: c-14.1,6 r0.75
  circle w1.5: c-15.25,11 r2.5
  circle w1.5: c-15.25,-11 r2.5
  circle w1.5: c15.25,-11 r2.5
  circle w1.5: c15.25,11 r2.5
  circle w1.5: c14.1,2 r0.75
  circle w1.5: c14.1,-2 r0.75
  circle w1.5: c14.1,-6 r0.75
  circle w1.5: c15.25,11 r1.2
  circle w1.5: c15.25,-11 r1.2
  circle w1.5: c-15.25,-11 r1.2
  circle w1.5: c-15.25,11 r1.2
  circle w1.5: c19,8.525 r1.3
  lines w1.5: -20.725,1.625 -19,1.625 ; -20.725,6.7 -19,6.7 ; -4.3,-2.2 11.3,-2.2 ; -4.3,-0.9 11.3,-0.9 ; 0.5,-11.2 11.7,-11.2 ; 0.5,-9.9 11.7,-9.9 ; 19,-6.7 20.725,-6.7 ; 19,-1.625 20.725,-1.625 ; 19,3.45 20.725,3.45 ; 19,7.225 20.725,7.225 20.725,9.075 19.975,9.825 19,9.825 ; 19,8.525 20.725,8.525 ; -20.725,0.325 -19,0.325 ccw(c-19,1.625) -19,2.925 -20.725,2.925 -20.725,0.325 ; -20.725,5.4 -20.725,8 -19,8 cw(c-19,6.7) -19,5.4 -20.725,5.4 ; -10.5,7.4 -10.5,13.2 -9.2,13.2 -9.2,7.4 -10.5,7.4 ; -4.3,-3.5 -4.3,0.4 11.3,0.4 11.3,-3.5 -4.3,-3.5 ; 0.5,-12.5 0.5,-8.6 11.7,-8.6 11.7,-12.5 0.5,-12.5 ; 9.2,7.4 9.2,13.2 10.5,13.2 10.5,7.4 9.2,7.4 ; 19,-8 cw(c19,-6.7) 19,-5.4 20.725,-5.4 20.725,-8 19,-8 ; 19,-2.925 cw(c19,-1.625) 19,-0.325 20.725,-0.325 20.725,-2.925 19,-2.925 ; 19,2.15 cw(c19,3.45) 19,4.75 20.725,4.75 20.725,2.15 19,2.15
  text "Anti-coating needle / diameter: 1.5 mm" at -26.154,-20.514 h1.52
  text "TOP Coating mask required" at -17,-24.27 h1.52
Bottom CoatingMask:
  circle w1.5: c19,-23 r0.75
  circle w1.5: c-14.1,2 r0.75
  circle w1.5: c-14.1,6 r0.75
  circle w1.5: c-15.25,11 r1.2
  circle w1.5: c-15.25,-11 r1.2
  circle w1.5: c15.25,-11 r1.2
  circle w1.5: c15.25,11 r2.5
  circle w1.5: c14.1,2 r0.75
  circle w1.5: c14.1,-2 r0.75
  circle w1.5: c14.1,-6 r0.75
  circle w1.5: c15.25,11 r1.2
  circle w1.5: c15.25,-11 r2.5
  circle w1.5: c-15.25,-11 r2.5
  circle w1.5: c-15.25,11 r2.5
  circle w1.5: c19,8.525 r1.3
  lines w1.5: -20.725,1.625 -19,1.625 ; -20.725,6.7 -19,6.7 ; -9.9,10.25 8.9,10.25 ; -7.4,-13.8 10.4,-13.8 ; -5.45,-10.25 8.35,-10.25 ; 19,-6.7 20.725,-6.7 ; 19,-1.625 20.725,-1.625 ; 19,3.45 20.725,3.45 ; 19,7.225 20.725,7.225 20.725,9.075 19.975,9.825 19,9.825 ; 19,8.525 20.725,8.525 ; -20.725,0.325 -20.725,2.925 -19,2.925 cw(c-19,1.625) -19,0.325 -20.725,0.325 ; -20.725,5.4 -20.725,8 -19,8 cw(c-19,6.7) -19,5.4 -20.725,5.4 ; -9.9,9.25 cw(c-9.9,10.25) -9.9,11.25 8.9,11.25 cw(c8.9,10.25) 8.9,9.25 -9.9,9.25 ; -5.45,-11.25 cw(c-5.45,-10.25) -5.45,-9.25 8.35,-9.25 cw(c8.35,-10.25) 8.35,-11.25 -5.45,-11.25 ; 19,-8 cw(c19,-6.7) 19,-5.4 20.725,-5.4 20.725,-8 19,-8 ; 19,-2.925 cw(c19,-1.625) 19,-0.325 20.725,-0.325 20.725,-2.925 19,-2.925 ; 19,2.15 cw(c19,3.45) 19,4.75 20.725,4.75 20.725,2.15 19,2.15
  text "Anti-coating needle / diameter: 1.5 mm" at 26.154,-20.514 h1.52
  text "BOT Coating mask required" at 17,-24.27 h1.52
Top CoatingMask_elective (Mech33):
  circle w1.5: c-19,-27 r0.75
  circle w1.5: c-15.25,-11 r1.2
  circle w1.5: c14.1,2 r0.75
  circle w1.5: c-14.1,6 r0.75
  circle w1.5: c-14.1,2 r0.75
  circle w1.5: c14.1,-2 r0.75
  circle w1.5: c14.1,2 r1
  circle w1.5: c14.1,-6 r0.75
  circle w1.5: c-15.25,11 r2.5
  circle w1.5: c-15.25,11 r1.2
  circle w1.5: c15.25,-11 r2.5
  circle w1.5: c15.25,-11 r1.2
  circle w1.5: c-15.25,-11 r2.5
  circle w1.5: c-15.25,-11 r0.6
  circle w1.5: c19,8.525 r1.3
  circle w1.5: c15.25,11 r1.2
  region: 17.4,9.1 17.4,3.008 17.392,3 14.3,3 11.7,0.4 11.7,-10.31 13.89,-12.5 17.25,-12.5 20.725,-9.025 20.725,9.075
  region: -9.2,13.2 -9.2,7.4 -12.7,7.4 -13.57,6.53 -13.57,2.53 -15.775,0.325 -20.725,0.325 -20.725,8.912 -16.437,13.2
  lines w1.5: -20.725,1.625 -19,1.625 ; -20.725,6.125 -20.725,0.325 ; -20.725,6.7 -19,6.7 ; -19.3,0.325 -15.775,0.325 -14.1,2 ; -16.9,12.9 -20.725,9.075 -20.725,8 ; -15.25,11 -12.75,11 ; -15.25,13.5 -9.2,13.5 -9.2,7.4 -10.5,7.4 ; -14.1,6 -12.7,7.4 -10.5,7.4 ; -13.35,2 -13.35,6 ; -9.2,13.2 -10.5,13.2 -10.5,7.4 ; -4.3,-2.2 11.3,-2.2 ; -4.3,-0.9 11.3,-0.9 ; 0.5,-11.2 11.7,-11.2 ; 0.5,-9.9 11.7,-9.9 ; 9.2,9.075 15,9.075 ; 9.2,13.2 10.5,13.2 10.5,7.4 9.2,7.4 9.2,13.5 15.25,13.5 ; 10.65,8.92 16.45,8.92 ; 10.67,11 15.25,11 ; 11.7,-3.5 14.3,-6.1 ; 11.7,0.4 14.3,3 18.68,3 ; 11.7,8.92 11.7,13.5 ; 12.1,-8.28 12.1,-3.9 ; 12.6,8.92 12.6,13.5 ; 13.863,8.92 cw(c15.25,11) 16.637,8.92 ; 14.3,-6 11.7,-8.6 ; 16.08,-12.5 11.7,-12.5 ; 17.25,-12.5 20.725,-9.025 20.725,-8 ; 17.375,12.425 19.975,9.825 ; 17.392,3.703 17.392,8.083 ; 19,-6.7 20.725,-6.7 ; 19,-1.625 20.725,-1.625 ; 19,3.45 20.725,3.45 ; 19,7.225 20.725,7.225 ; 19,8.525 20.725,8.525 ; 19,9.825 19.975,9.825 ; 20.725,-7.305 20.725,-2.925 ; 20.725,-2.23 20.725,2.15 ; 20.725,2.845 20.725,7.225 ; -20.725,0.325 -20.725,2.925 -19,2.925 cw(c-19,1.625) -19,0.325 -20.725,0.325 ; -20.725,8 -19,8 cw(c-19,6.7) -19,5.4 -20.725,5.4 -20.725,8 ; 11.7,-12.5 11.7,-8.6 ; 11.7,-12.5 0.5,-12.5 0.5,-8.6 11.7,-8.6 ; 19.975,9.825 20.725,9.075 20.725,7.225 ; 20.725,-8 20.725,-5.4 19,-5.4 ccw(c19,-6.7) 19,-8 20.725,-8 ; 20.725,-2.925 19,-2.925 cw(c19,-1.625) 19,-0.325 20.725,-0.325 20.725,-2.925 ; 20.725,2.15 20.725,4.75 19,4.75 ccw(c19,3.45) 19,2.15 20.725,2.15 ; -4.3,-3.5 -4.3,0.4 11.3,0.4 11.3,-3.5 -4.3,-3.5
  text "TOP Coating mask elective" at -17,-28.27 h1.52
Bottom CoatingMask_elective (Mech34):
  circle w1.5: c19,-27 r0.75
  circle w1.5: c-15.25,11 r2.5
  circle w1.5: c-14.1,6 r0.75
  circle w1.5: c-14.1,2 r0.75
  circle w1.5: c19,8.525 r1.3
  circle w1.5: c14.1,2 r0.75
  circle w1.5: c15.25,11 r2.5
  circle w1.5: c15.25,11 r1.2
  circle w1.5: c15.25,-11 r2.5
  circle w1.5: c-15.25,-11 r2.5
  circle w1.5: c15.25,-11 r1.2
  circle w1.5: c-15.25,-11 r1.2
  circle w1.5: c-15.25,11 r1.2
  circle w1.5: c14.1,-2 r0.75
  circle w1.5: c14.1,-6 r0.75
  region: -14.05,11 -14.05,6.397 -13.35,5.697 -13.35,2 -14.098,1.252 -16.448,1.252 -17.15,0.55 -17.2,0.6 -20.5,0.6 -20.5,9.192 -17.375,12.317
  region: 14.9,11.2 14.9,9.228 17.2,6.928 17.2,3.5 16.435,2.735 14.25,2.735 13.365,1.85 13.365,-12.8 17,-12.8 20.725,-9.075 20.725,9.075 18.55,11.25
  lines w1.5: -20.725,1.625 -19,1.625 ; -20.725,6.7 -19,6.7 ; -17.15,12.625 -20.725,9.05 -20.725,8 ; -15.25,-12.05 -15.25,-11 ; -15.25,11 -13.653,9.403 ; -14.1,8.78 -14.1,7.049 -13.653,6.602 ; -14.05,1.252 -16.448,1.252 -17.375,0.325 -19,0.325 ; -13.465,9.25 -9.9,9.25 ; -13.465,9.325 -11.54,11.25 -9.9,11.25 ; -13.35,2 -13.35,6 ; -13.35,12.625 -10.975,10.25 -9.9,10.25 8.9,10.25 19.55,10.25 ; 8.35,-10.25 -5.45,-10.25 -7.4,-12.2 -7.4,-13.8 16,-13.8 17.75,-12.05 ; 12.763,-13.8 12.763,-10.75 ; 12.763,11.25 8.9,11.25 ; 13.365,-9.25 13.365,2.15 ; 14.25,2.735 16.435,2.735 17.2,3.5 17.2,6.928 15.603,8.525 ; 15.25,-12.05 15.25,-11 ; 15.25,11 16.847,9.403 ; 16.9,12.9 19.55,10.25 ; 17,-12.8 20.725,-9.075 20.725,8.15 ; 19,-6.7 20.725,-6.7 ; 19,-1.625 20.725,-1.625 ; 19,3.45 20.725,3.45 ; 19,7.225 20.725,7.225 20.725,9.075 19.975,9.825 19,9.825 ; 19,8.525 20.725,8.525 ; 20.55,9.25 19.55,10.25 ; -20.725,2.925 -20.725,5.4 ; -20.725,2.925 -20.725,0.325 -19,0.325 ; -20.725,2.925 -19,2.925 cw(c-19,1.625) -19,0.325 ; -20.725,5.4 -19,5.4 ccw(c-19,6.7) -19,8 -20.725,8 ; -20.725,5.4 -20.725,8 ; -9.9,9.25 cw(c-9.9,10.25) -9.9,11.25 ; -9.9,9.25 8.9,9.25 ccw(c8.9,10.25) 8.9,11.25 ; -9.9,11.25 8.9,11.25 ; -5.45,-11.25 cw(c-5.45,-10.25) -5.45,-9.25 8.35,-9.25 cw(c8.35,-10.25) 8.35,-11.25 -5.45,-11.25 ; 19,-8 cw(c19,-6.7) 19,-5.4 20.725,-5.4 20.725,-8 19,-8 ; 19,-2.925 cw(c19,-1.625) 19,-0.325 20.725,-0.325 20.725,-2.925 19,-2.925 ; 19,2.15 cw(c19,3.45) 19,4.75 20.725,4.75 20.725,2.15 19,2.15
  text "BOT Coating mask elective" at 17,-28.27 h1.52

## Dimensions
132.5,-22 to -28.5,-22 on Mechanical 16
54.5,-14.5 to 53.5,14.5 on Mechanical 16
73,-2 to 31,-2.5 on Mechanical 16
123.5,102.5 to 123.5,92.5 on Mechanical 16
123.5,63.5 to 123.5,53.5 on Mechanical 16
123.5,24.5 to 123.5,14.5 on Mechanical 16
135.5,-22 to 123.5,-14.5 on Mechanical 16
83,-11 to 73,-11 on Mechanical 16
132.5,-23.5 to 125,-12 on Mechanical 16
21,-11.5 to 31,-11.5 on Mechanical 16
132.5,139 to 123.5,136 on Mechanical 16
132.5,139 to 129.5,130 on Mechanical 16
132.5,139 to 129.5,130 on Mechanical 16
132.5,139 to 123.5,136 on Mechanical 16
132.5,139 to 132.5,-22 on Mechanical 16
104,117 to 132.5,139 on Mechanical 16
104,78 to 104,117 on Mechanical 16
104,39 to 104,78 on Mechanical 16
104,0 to 104,39 on Mechanical 16
132.5,-22 to 104,0 on Mechanical 16
132.5,-22 to 131,-19 on Mechanical 16
132.5,-22 to 129.5,-20.5 on Mechanical 16
104,0 to 132.5,-22 on Mechanical 16
0,0 to -28.5,-22 on Mechanical 16
-19.5,-19 to -28.5,-22 on Mechanical 16
-28.5,-22 to -25.5,-13 on Mechanical 16
52,0 to 104,0 on Mechanical 16
0,0 to 52,0 on Mechanical 16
